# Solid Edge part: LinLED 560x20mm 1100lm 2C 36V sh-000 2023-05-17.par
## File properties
Author: jaroslaw.przewlocki
Template: iso metric part.par
Last saved by: jaroslaw.przewlocki
Revision: 1
Application: Solid Edge
Gęstość: 0,000 kg/m^3
Dokładność: 0,990
Username: jaroslaw.przewlocki
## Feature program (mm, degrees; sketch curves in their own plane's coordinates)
body "unnamed Body 1"
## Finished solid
Body 1: solid body, 1142 faces, 2974 edges, 1924 vertices.
  Faces by surface: plane 822, cylinder 164, torus 64, cone 50, spline 26, sphere 16
  Edges by curve: line 2298, curve on surface 356, circle 218, ellipse 66, spline 36
Bounding box of the edges (mm; curved faces can reach further): 559.600 x 20.000 x 4.450, from (-279.8, -10, -1) to (279.8, 10, 3.45).
Cylindrical faces by radius (mm): R0.2 x46, R0.2169 x6, R0.25 x32, R0.3373 x6, R0.4 x8, R0.4006 x2, R0.4008 x2, R0.525 x2, R0.6 x20, R1 x12, R1.1 x4, R1.1989 x2, R1.199 x2, R1.2 x10, R2.15 x10
Conical faces (half-angle, radius in mm at the cone's reference point): 0.398 deg R1.1964 x2, 0.4493 deg R1.1964 x2, 0.4746 deg R1.1948 x2, 0.4758 deg R1.1948 x2, 0.5 deg R0.5056 x4, 0.5 deg R1.0082 x4, 1 deg R0.5511 x2, 10 deg R0.2132 x4, 10 deg R0.4132 x4, 16.0099 deg R1.1053 x2, 16.1249 deg R1.1279 x2, 18.8604 deg R1.0669 x4, 19.5041 deg R0.5138 x2, 19.8244 deg R0.5099 x2, 27.363 deg R0.6214 x2, 40.6434 deg R0.5161 x2, 43.3309 deg R0.4892 x2, 45 deg R0.575 x2, 45 deg R0.625 x4
Toroidal faces (ring radius, tube radius in mm): R0.0958 r0.3997 x4, R0.1076 r0.4 x2, R0.1101 r0.4001 x2, R0.1217 r0.4 x2, R0.1234 r0.4 x2, R0.1626 r0.228 x2, R0.1634 r0.2287 x2, R0.3287 r0.2001 x2, R0.3684 r0.2151 x2, R0.3703 r0.4 x2, R0.3818 r0.2 x4, R0.4166 r0.3983 x2, R0.5981 r0.197 x2, R0.5982 r0.197 x2, R0.6009 r0.3968 x2, R0.6009 r0.3969 x2, R0.6227 r0.2 x2, R0.6235 r0.2 x2, R0.8 r0.2 x4, R0.8522 r0.3 x2, R0.9002 r0.2 x2, R0.9018 r0.2 x2, R0.9197 r0.223 x2, R0.9365 r0.2 x2, R0.9663 r0.2263 x2, R0.9665 r0.2263 x2, R1.429 r1.2 x2, R1.8741 r0.2175 x2, R1.9007 r0.2 x2
Spherical faces by radius (mm): R0.2 x12, R0.6 x4
Planar faces by outward normal: +x 98, +y 103, +z 133, -x 98, -y 105, -z 9, oblique 276
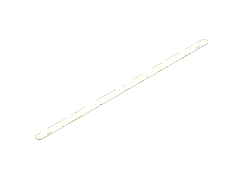
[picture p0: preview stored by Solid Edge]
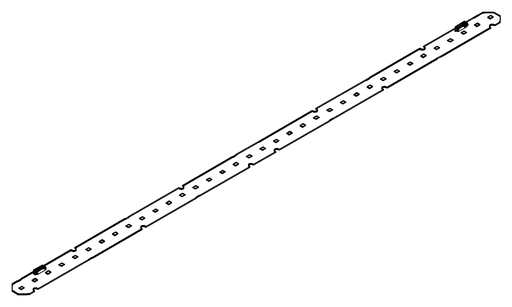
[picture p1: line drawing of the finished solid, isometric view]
